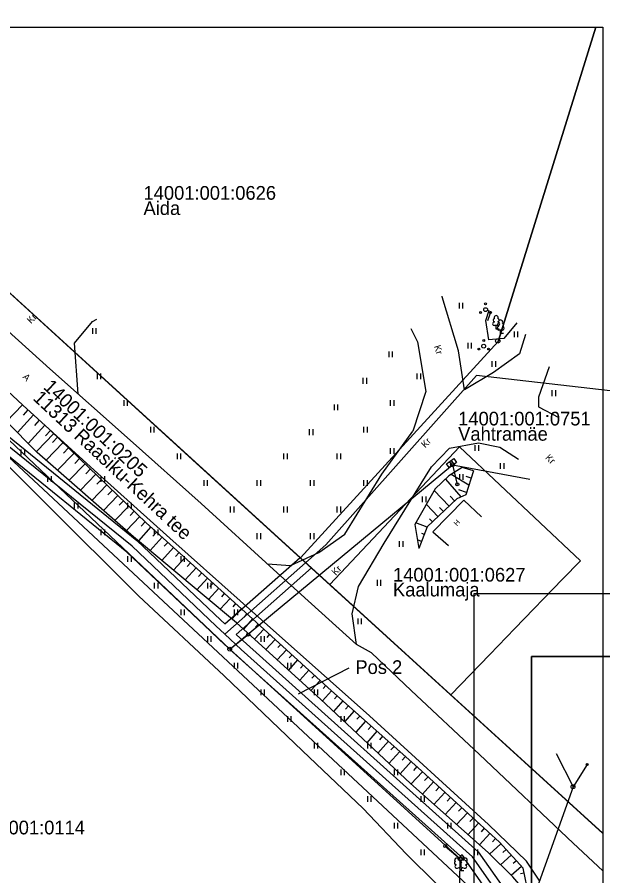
# Model space of a CAD drawing. Extents: x 567864 to 568657, y 6579839 to 6580994.
# Drawn here: x 568307.8 to 568384.7, y 6580491.9 to 6580604.7 of the extents above; entities that cross this region are included whole.
import ezdxf

# ---------------------------------------------------------------- set-up
doc = ezdxf.new("R2010")
doc.units = 0
for name, color, linetype in [('ELRAJATISMP', 7, 'Continuous'), ('HALJASTUS', 7, 'Continuous'), ('HOONE', 7, 'Continuous'), ('KASUTUSALA', 7, 'Continuous'), ('MPKAABEL', 7, 'Continuous'), ('MPOHULIIN', 7, 'Continuous'), ('PIIR', 7, 'Continuous'), ('PIIRIMLEITUD', 7, 'Continuous'), ('POST', 7, 'Continuous'), ('PR_SIDE', 7, 'Continuous'), ('PUU', 7, 'Continuous'), ('RELJEEF', 7, 'Continuous'), ('TEE', 7, 'Continuous'), ('VORMISTUS_2', 7, 'Continuous'), ('VORMISTUS_3', 7, 'Continuous')]:
    doc.layers.add(name, color=color, linetype=linetype)

msp = doc.modelspace()

# ---------------------------------------------------------------- linework, layer by layer
at = {"layer": 'ELRAJATISMP'}
for p, q in [((568364.53, 6580546.27), (568364.87, 6580545.78)), ((568364.75, 6580546.42), (568365.09, 6580545.94))]:
    msp.add_line(p, q, dxfattribs=at)
msp.add_lwpolyline([(568364.15, 6580546), (568365.13, 6580546.69), (568365.47, 6580546.2), (568364.49, 6580545.51)], close=True, dxfattribs=at)
at = {"layer": 'HALJASTUS'}
for p, q in [((568365.81, 6580567.15), (568365.81, 6580566.39)), ((568366.27, 6580567.15), (568366.27, 6580566.39)), ((568317.67, 6580563.82), (568317.67, 6580563.06)), ((568318.13, 6580563.82), (568318.13, 6580563.06)), ((568373.04, 6580563.4), (568373.04, 6580562.64)), ((568373.49, 6580563.4), (568373.49, 6580562.64)), ((568366.94, 6580561.91), (568366.94, 6580561.15)), ((568367.39, 6580561.91), (568367.39, 6580561.15)), ((568356.58, 6580560.76), (568356.58, 6580560)), ((568357.03, 6580560.76), (568357.03, 6580560)), ((568370.13, 6580559.5), (568370.13, 6580558.74)), ((568370.59, 6580559.5), (568370.59, 6580558.74)), ((568318.27, 6580557.88), (568318.27, 6580557.12)), ((568318.73, 6580557.88), (568318.73, 6580557.12)), ((568360.27, 6580557.88), (568360.27, 6580557.12)), ((568360.73, 6580557.88), (568360.73, 6580557.12)), ((568353.19, 6580557.28), (568353.19, 6580556.52)), ((568353.64, 6580557.28), (568353.64, 6580556.52)), ((568378, 6580555.66), (568378, 6580554.9)), ((568378.45, 6580555.66), (568378.45, 6580554.9)), ((568321.77, 6580554.38), (568321.77, 6580553.62)), ((568322.23, 6580554.38), (568322.23, 6580553.62)), ((568356.77, 6580554.38), (568356.77, 6580553.62)), ((568357.23, 6580554.38), (568357.23, 6580553.62)), ((568349.4, 6580553.81), (568349.4, 6580553.05)), ((568349.86, 6580553.81), (568349.86, 6580553.05)), ((568325.27, 6580550.88), (568325.27, 6580550.12)), ((568325.73, 6580550.88), (568325.73, 6580550.12)), ((568353.27, 6580550.88), (568353.27, 6580550.12)), ((568353.73, 6580550.88), (568353.73, 6580550.12)), ((568346.13, 6580550.54), (568346.13, 6580549.78)), ((568346.59, 6580550.54), (568346.59, 6580549.78)), ((568367.89, 6580548.45), (568367.89, 6580547.69)), ((568368.34, 6580548.45), (568368.34, 6580547.69)), ((568308.27, 6580547.88), (568308.27, 6580547.12)), ((568308.73, 6580547.88), (568308.73, 6580547.12)), ((568328.77, 6580547.38), (568328.77, 6580546.62)), ((568329.23, 6580547.38), (568329.23, 6580546.62)), ((568342.77, 6580547.38), (568342.77, 6580546.62)), ((568343.23, 6580547.38), (568343.23, 6580546.62)), ((568349.77, 6580547.38), (568349.77, 6580546.62)), ((568350.23, 6580547.38), (568350.23, 6580546.62)), ((568356.77, 6580548.07), (568356.77, 6580547.31)), ((568357.23, 6580548.07), (568357.23, 6580547.31)), ((568371.22, 6580546.1), (568371.22, 6580545.34)), ((568371.68, 6580546.1), (568371.68, 6580545.34)), ((568311.77, 6580544.38), (568311.77, 6580543.62)), ((568312.23, 6580544.38), (568312.23, 6580543.62)), ((568318.77, 6580544.38), (568318.77, 6580543.62)), ((568319.23, 6580544.38), (568319.23, 6580543.62)), ((568365.86, 6580544.65), (568365.86, 6580543.89)), ((568366.31, 6580544.65), (568366.31, 6580543.89)), ((568332.27, 6580543.88), (568332.27, 6580543.12)), ((568332.73, 6580543.88), (568332.73, 6580543.12)), ((568339.27, 6580543.88), (568339.27, 6580543.12)), ((568339.73, 6580543.88), (568339.73, 6580543.12)), ((568346.27, 6580543.88), (568346.27, 6580543.12)), ((568346.73, 6580543.88), (568346.73, 6580543.12)), ((568353.27, 6580543.88), (568353.27, 6580543.12)), ((568353.73, 6580543.88), (568353.73, 6580543.12)), ((568360.98, 6580541.72), (568360.98, 6580540.96)), ((568361.43, 6580541.72), (568361.43, 6580540.96)), ((568315.27, 6580540.88), (568315.27, 6580540.12)), ((568315.73, 6580540.88), (568315.73, 6580540.12)), ((568322.27, 6580540.88), (568322.27, 6580540.12)), ((568322.73, 6580540.88), (568322.73, 6580540.12)), ((568335.77, 6580540.38), (568335.77, 6580539.62)), ((568336.23, 6580540.38), (568336.23, 6580539.62)), ((568342.77, 6580540.38), (568342.77, 6580539.62)), ((568343.23, 6580540.38), (568343.23, 6580539.62)), ((568349.77, 6580540.38), (568349.77, 6580539.62)), ((568350.23, 6580540.38), (568350.23, 6580539.62)), ((568318.77, 6580537.38), (568318.77, 6580536.62)), ((568319.23, 6580537.38), (568319.23, 6580536.62)), ((568325.77, 6580537.38), (568325.77, 6580536.62)), ((568326.23, 6580537.38), (568326.23, 6580536.62)), ((568339.27, 6580536.88), (568339.27, 6580536.12)), ((568339.73, 6580536.88), (568339.73, 6580536.12)), ((568346.27, 6580536.88), (568346.27, 6580536.12)), ((568346.73, 6580536.88), (568346.73, 6580536.12)), ((568357.96, 6580535.87), (568357.96, 6580535.11)), ((568358.41, 6580535.87), (568358.41, 6580535.11)), ((568322.27, 6580533.88), (568322.27, 6580533.12)), ((568322.73, 6580533.88), (568322.73, 6580533.12)), ((568329.27, 6580533.88), (568329.27, 6580533.12)), ((568329.73, 6580533.88), (568329.73, 6580533.12)), ((568355.04, 6580530.76), (568355.04, 6580529.99)), ((568355.49, 6580530.76), (568355.49, 6580529.99)), ((568325.77, 6580530.38), (568325.77, 6580529.62)), ((568326.23, 6580530.38), (568326.23, 6580529.62)), ((568332.77, 6580530.38), (568332.77, 6580529.62)), ((568333.23, 6580530.38), (568333.23, 6580529.62)), ((568329.27, 6580526.88), (568329.27, 6580526.12)), ((568329.73, 6580526.88), (568329.73, 6580526.12)), ((568336.27, 6580526.88), (568336.27, 6580526.12)), ((568336.73, 6580526.88), (568336.73, 6580526.12)), ((568352.52, 6580525.69), (568352.52, 6580524.93)), ((568352.97, 6580525.69), (568352.97, 6580524.93)), ((568332.77, 6580523.38), (568332.77, 6580522.62)), ((568333.23, 6580523.38), (568333.23, 6580522.62)), ((568339.77, 6580523.38), (568339.77, 6580522.62)), ((568340.23, 6580523.38), (568340.23, 6580522.62)), ((568336.27, 6580519.88), (568336.27, 6580519.12)), ((568336.73, 6580519.88), (568336.73, 6580519.12)), ((568343.27, 6580519.88), (568343.27, 6580519.12)), ((568343.73, 6580519.88), (568343.73, 6580519.12)), ((568339.77, 6580516.38), (568339.77, 6580515.62)), ((568340.23, 6580516.38), (568340.23, 6580515.62)), ((568346.77, 6580516.38), (568346.77, 6580515.62)), ((568347.23, 6580516.38), (568347.23, 6580515.62)), ((568343.27, 6580512.88), (568343.27, 6580512.12)), ((568343.73, 6580512.88), (568343.73, 6580512.12)), ((568350.27, 6580512.88), (568350.27, 6580512.12)), ((568350.73, 6580512.88), (568350.73, 6580512.12)), ((568346.77, 6580509.38), (568346.77, 6580508.62)), ((568347.23, 6580509.38), (568347.23, 6580508.62)), ((568353.77, 6580509.38), (568353.77, 6580508.62)), ((568354.23, 6580509.38), (568354.23, 6580508.62)), ((568350.27, 6580505.88), (568350.27, 6580505.12)), ((568350.73, 6580505.88), (568350.73, 6580505.12)), ((568357.27, 6580505.88), (568357.27, 6580505.12)), ((568357.73, 6580505.88), (568357.73, 6580505.12)), ((568353.77, 6580502.38), (568353.77, 6580501.62)), ((568354.23, 6580502.38), (568354.23, 6580501.62)), ((568360.77, 6580502.38), (568360.77, 6580501.62)), ((568361.23, 6580502.38), (568361.23, 6580501.62)), ((568357.27, 6580498.88), (568357.27, 6580498.12)), ((568357.73, 6580498.88), (568357.73, 6580498.12)), ((568364.27, 6580498.88), (568364.27, 6580498.12)), ((568364.73, 6580498.88), (568364.73, 6580498.12)), ((568360.77, 6580495.38), (568360.77, 6580494.62)), ((568361.23, 6580495.38), (568361.23, 6580494.62)), ((568367.77, 6580495.38), (568367.77, 6580494.62)), ((568368.23, 6580495.38), (568368.23, 6580494.62))]:
    msp.add_line(p, q, dxfattribs=at)
for points in [[(568373.39, 6580564.53), (568371.7, 6580562.45), (568369.73, 6580562.3), (568369.32, 6580564.83), (568369.76, 6580566.16)], [(568369.59, 6580564.81), (568370.01, 6580566.05)]]:
    msp.add_lwpolyline(points, dxfattribs=at)
at = {"layer": 'HOONE'}
msp.add_lwpolyline([(568368.77, 6580539.04), (568366.43, 6580541.23), (568362.38, 6580537.07), (568364.42, 6580535.26)], dxfattribs=at)
at = {"layer": 'KASUTUSALA'}
msp.add_lwpolyline([(568371.56, 6580487.01), (568366.82, 6580493.74), (568336.54, 6580520.89), (568334.37, 6580522.89), (568333.16, 6580524.02), (568322.19, 6580534.42), (568305.67, 6580547.79), (568289.57, 6580562.8), (568275.19, 6580576.52), (568283.17, 6580571.11), (568291.95, 6580563.33), (568305.08, 6580550.84), (568323.51, 6580535.93), (568334.54, 6580525.48), (568335.07, 6580524.98), (568344.93, 6580533.71), (568344.98, 6580533.67), (568346.42, 6580532.36), (568336.55, 6580523.61), (568337.05, 6580523.13), (568337.88, 6580522.37), (568368.32, 6580495.08), (568373.24, 6580488.09)], dxfattribs=at)
at = {"layer": 'MPKAABEL'}
msp.add_lwpolyline([(568290.51, 6580580.15), (568289.47, 6580579.17), (568285.16, 6580574.37), (568283.84, 6580573.07), (568282.41, 6580571.53), (568281.92, 6580570.15), (568282.67, 6580568.89), (568289.46, 6580562.85), (568299.87, 6580552.42), (568311.62, 6580540.71), (568323.73, 6580528.68), (568334.96, 6580518.16), (568345.24, 6580508.32), (568353.21, 6580500.74), (568358.87, 6580494.79), (568362.88, 6580490.81), (568367.26, 6580487.78), (568369.74, 6580485.8), (568369.72, 6580484.3), (568368.69, 6580483.14), (568367.08, 6580481.93), (568366.32, 6580481.93), (568366.01, 6580481.86)], dxfattribs=at)
at = {"layer": 'MPOHULIIN'}
for points in [[(568335.69, 6580521.66), (568305, 6580550.67), (568273.62, 6580580.19), (568260.93, 6580591.97)], [(568365.79, 6580481.37), (568365.95, 6580494.12), (568335.69, 6580521.66), (568364.95, 6580545.89), (568375.08, 6580544.01)], [(568378.55, 6580507.96), (568380.77, 6580503.61), (568373.44, 6580483.03)]]:
    msp.add_lwpolyline(points, dxfattribs=at)
at = {"layer": 'PIIR'}
for points in [[(568268.46, 6580603.35), (568287.11, 6580586.34), (568330.81, 6580546.53), (568384.68, 6580497.48)], [(568383.76, 6580603.35), (568370.95, 6580562.05), (568344.98, 6580533.67), (568287.11, 6580586.34), (568302.89, 6580603.35)], [(568384.68, 6580497.49), (568364.73, 6580515.67), (568369.83, 6580520.95), (568373.15, 6580524.39), (568379.4, 6580530.86), (568381.74, 6580533.28), (568365.86, 6580548.23), (568348.84, 6580530.15), (568344.98, 6580533.67), (568370.95, 6580562.05), (568383.76, 6580603.35)], [(568384.68, 6580474.14), (568373.5, 6580484.56), (568289.57, 6580562.8), (568260.93, 6580590.14)], [(568260.93, 6580487.5), (568289.57, 6580562.8), (568373.5, 6580484.56), (568310.3, 6580445.85)]]:
    msp.add_lwpolyline(points, dxfattribs=at)
msp.add_lwpolyline([(568348.84, 6580530.15), (568365.86, 6580548.23), (568381.74, 6580533.28), (568379.4, 6580530.86), (568373.15, 6580524.39), (568369.83, 6580520.95), (568364.73, 6580515.67)], close=True, dxfattribs=at)
at = {"layer": 'PIIRIMLEITUD'}
msp.add_circle((568370.88, 6580562.14), 0.285, dxfattribs=at)
at = {"layer": 'POST'}
for p, q in [((568366.22, 6580494.65), (568365.99, 6580494.47)), ((568366.3, 6580494.07), (568365.99, 6580494.47)), ((568366.53, 6580494.25), (568366.22, 6580494.65)), ((568366.53, 6580494.25), (568366.3, 6580494.07))]:
    msp.add_line(p, q, dxfattribs=at)
for points in [[(568364.95, 6580545.89), (568365.58, 6580543.31)], [(568335.69, 6580521.66), (568338.13, 6580523.59)], [(568382.63, 6580506.54), (568380.77, 6580503.61)], [(568363.99, 6580495.82), (568365.95, 6580494.12)]]:
    msp.add_lwpolyline(points, dxfattribs=at)
for centre, radius in [((568364.95, 6580545.89), 0.25), ((568365.58, 6580543.31), 0.2), ((568338.13, 6580523.59), 0.2), ((568335.69, 6580521.66), 0.25), ((568382.63, 6580506.54), 0.125), ((568382.63, 6580506.54), 0.105), ((568382.63, 6580506.54), 0.0851), ((568382.63, 6580506.54), 0.0651), ((568382.63, 6580506.54), 0.0451), ((568382.63, 6580506.54), 0.0251), ((568382.63, 6580506.54), 0.00511), ((568380.77, 6580503.61), 0.25), ((568363.99, 6580495.82), 0.2), ((568365.95, 6580494.12), 0.25)]:
    msp.add_circle(centre, radius, dxfattribs=at)
at = {"layer": 'PR_SIDE'}
for points in [[(568372.77, 6580480.66), (568372.77, 6580480.66), (568372.77, 6580480.66), (568373.4, 6580481.36), (568374.25, 6580482.51), (568374.05, 6580484.04), (568373.82, 6580485.15), (568372.4, 6580487.55), (568367.57, 6580494.41), (568337.21, 6580521.63), (568335.06, 6580523.62), (568333.85, 6580524.75), (568322.86, 6580535.18), (568304.42, 6580550.09), (568291.27, 6580562.6), (568282.56, 6580570.32), (568277.09, 6580574.03), (568269.58, 6580580.5), (568245.73, 6580603.12), (568233.69, 6580614.91)], [(568401.09, 6580556.96), (568388.3, 6580555.28), (568368.11, 6580557.62), (568348.32, 6580535.38), (568335.06, 6580523.62)]]:
    msp.add_lwpolyline(points, dxfattribs=at)
at = {"layer": 'PUU'}
for p, q in [((568370.92, 6580564.15), (568370.44, 6580564.15)), ((568370.68, 6580563.67), (568370.68, 6580564.15)), ((568371.06, 6580563.67), (568370.68, 6580563.67)), ((568371.5, 6580563.57), (568371.02, 6580563.57)), ((568371.26, 6580563.1), (568371.26, 6580563.57)), ((568371.64, 6580563.1), (568371.26, 6580563.1)), ((568365.6, 6580492.91), (568366.04, 6580493.09)), ((568366.04, 6580492.58), (568365.86, 6580493.02)), ((568366.04, 6580493.09), (568366.48, 6580492.91)), ((568366.04, 6580492.58), (568366.22, 6580493.02)), ((568366.42, 6580492.58), (568366.04, 6580492.58))]:
    msp.add_line(p, q, dxfattribs=at)
msp.add_lwpolyline([(568366.04, 6580493.58), (568366.02, 6580493.51), (568366.02, 6580493.49), (568366.03, 6580493.46), (568366.05, 6580493.42), (568366.06, 6580493.4), (568366.04, 6580493.37), (568366.02, 6580493.32), (568366.01, 6580493.29), (568366.02, 6580493.28), (568366.03, 6580493.25), (568366.06, 6580493.19), (568366.07, 6580493.17), (568366.06, 6580493.15), (568366.05, 6580493.11), (568366.04, 6580493.09)], dxfattribs=at)
for centre, radius in [((568369.29, 6580566.25), 0.25), ((568369.29, 6580567), 0.125), ((568368.64, 6580565.87), 0.125), ((568369.94, 6580565.87), 0.125), ((568369.04, 6580562.2), 0.125), ((568368.39, 6580561.08), 0.125), ((568369.04, 6580561.45), 0.25), ((568369.69, 6580561.08), 0.125)]:
    msp.add_circle(centre, radius, dxfattribs=at)
for centre, radius, start, end in [((568370.68, 6580565.19), 0.277, 332.5799, 207.4201), ((568370.44, 6580564.39), 0.238, 90.0016, 269.3953), ((568370.51, 6580564.85), 0.233, 109.0217, 253.1415), ((568371.09, 6580564.27), 0.233, 109.0217, 253.1415), ((568370.85, 6580564.85), 0.233, 286.8508, 70.9859), ((568370.91, 6580564.39), 0.238, 270.6047, 89.9984), ((568371.26, 6580564.62), 0.277, 332.5799, 207.4201), ((568371.43, 6580564.27), 0.233, 286.8508, 70.9859), ((568371.03, 6580563.81), 0.238, 90.0016, 269.3953), ((568371.5, 6580563.81), 0.238, 270.6047, 89.9984), ((568365.41, 6580493.58), 0.224, 111.4304, 274.4987), ((568365.48, 6580493.99), 0.256, 111.5027, 232.5173), ((568365.51, 6580493.14), 0.237, 111.5014, 291.5004), ((568365.48, 6580493.99), 0.256, 350.4856, 111.5002), ((568365.82, 6580493.74), 0.224, 308.5041, 111.5725), ((568366.04, 6580493.34), 0.237, 66.7655, 111.5015), ((568366.28, 6580493.74), 0.225, 67.7016, 230.5126), ((568366.62, 6580493.98), 0.256, 67.6168, 188.6314), ((568366.57, 6580493.13), 0.237, 247.6166, 67.6155), ((568366.69, 6580493.57), 0.224, 264.6183, 67.6866), ((568366.62, 6580493.98), 0.256, 306.5997, 67.6143)]:
    msp.add_arc(centre, radius, start, end, dxfattribs=at)
at = {"layer": 'RELJEEF'}
for p, q in [((568308.46, 6580553.77), (568306.39, 6580551.54)), ((568309.2, 6580553.09), (568308.58, 6580552.41)), ((568309.94, 6580552.42), (568307.83, 6580550.1)), ((568311.42, 6580551.07), (568309.24, 6580548.68)), ((568310.68, 6580551.75), (568310.04, 6580551.04)), ((568312.59, 6580549.98), (568310.36, 6580547.66)), ((568312.16, 6580550.4), (568311.49, 6580549.67)), ((568313.81, 6580548.8), (568311.58, 6580546.49)), ((568313.09, 6580549.5), (568312.41, 6580548.79)), ((568315.25, 6580547.41), (568313.08, 6580545.17)), ((568314.53, 6580548.11), (568313.87, 6580547.42)), ((568315.97, 6580546.72), (568315.33, 6580546.05)), ((568316.69, 6580546.02), (568314.59, 6580543.85)), ((568317.41, 6580545.33), (568316.79, 6580544.69)), ((568367.71, 6580545.09), (568367.71, 6580545.09)), ((568318.13, 6580544.63), (568316.09, 6580542.53)), ((568318.84, 6580543.94), (568318.25, 6580543.32)), ((568366.07, 6580541.65), (568364.05, 6580544.01)), ((568367.09, 6580543.19), (568364.78, 6580544.6)), ((568367.4, 6580544.14), (568366.74, 6580544.36)), ((568319.56, 6580543.24), (568317.6, 6580541.21)), ((568321, 6580541.85), (568319.1, 6580539.89)), ((568320.28, 6580542.55), (568319.7, 6580541.95)), ((568364.51, 6580540.43), (568362.56, 6580542.49)), ((568365.24, 6580541.11), (568364.64, 6580541.75)), ((568366.78, 6580542.24), (568365.76, 6580542.58)), ((568321.72, 6580541.16), (568321.16, 6580540.58)), ((568363.06, 6580539.05), (568361.53, 6580540.67)), ((568322.44, 6580540.46), (568320.61, 6580538.57)), ((568323.16, 6580539.77), (568322.62, 6580539.21)), ((568363.78, 6580539.74), (568363.26, 6580540.29)), ((568323.88, 6580539.07), (568322.12, 6580537.25)), ((568324.6, 6580538.38), (568324.08, 6580537.84)), ((568362.33, 6580538.37), (568361.93, 6580538.79)), ((568325.34, 6580537.71), (568323.7, 6580535.89)), ((568361.62, 6580537.67), (568360.15, 6580538.24)), ((568326.82, 6580536.36), (568325.23, 6580534.61)), ((568326.08, 6580537.03), (568325.59, 6580536.5)), ((568361.26, 6580536.74), (568360.93, 6580536.86)), ((568328.31, 6580535.02), (568326.77, 6580533.32)), ((568327.56, 6580535.69), (568327.09, 6580535.18)), ((568360.89, 6580535.81), (568360.35, 6580536.02)), ((568329.05, 6580534.35), (568328.59, 6580533.85)), ((568329.79, 6580533.68), (568328.3, 6580532.04)), ((568330.53, 6580533.01), (568330.09, 6580532.53)), ((568331.27, 6580532.34), (568329.84, 6580530.76)), ((568332.02, 6580531.67), (568331.59, 6580531.2)), ((568332.76, 6580531), (568331.38, 6580529.47)), ((568334.24, 6580529.66), (568332.91, 6580528.19)), ((568333.5, 6580530.33), (568333.09, 6580529.88)), ((568335.73, 6580528.32), (568334.45, 6580526.91)), ((568334.98, 6580528.99), (568334.59, 6580528.56)), ((568336.47, 6580527.65), (568336.09, 6580527.23)), ((568337.21, 6580526.98), (568335.98, 6580525.62)), ((568337.95, 6580526.31), (568337.59, 6580525.91)), ((568338.69, 6580525.63), (568337.48, 6580524.31)), ((568339.43, 6580524.96), (568339.07, 6580524.56)), ((568340.17, 6580524.29), (568338.96, 6580522.96)), ((568341.65, 6580522.94), (568340.44, 6580521.62)), ((568340.91, 6580523.62), (568340.55, 6580523.22)), ((568343.13, 6580521.6), (568341.92, 6580520.27)), ((568342.39, 6580522.27), (568342.03, 6580521.87)), ((568344.61, 6580520.25), (568343.4, 6580518.93)), ((568343.87, 6580520.92), (568343.51, 6580520.53)), ((568345.35, 6580519.58), (568344.99, 6580519.18)), ((568346.09, 6580518.9), (568344.88, 6580517.58)), ((568346.83, 6580518.23), (568346.47, 6580517.84)), ((568347.57, 6580517.56), (568346.36, 6580516.24)), ((568348.31, 6580516.89), (568347.95, 6580516.49)), ((568349.05, 6580516.21), (568347.86, 6580514.87)), ((568350.54, 6580514.88), (568349.31, 6580513.5)), ((568349.79, 6580515.55), (568349.43, 6580515.14)), ((568352.04, 6580513.56), (568350.77, 6580512.13)), ((568351.29, 6580514.22), (568350.91, 6580513.8)), ((568352.78, 6580512.89), (568352.4, 6580512.46)), ((568353.53, 6580512.23), (568352.23, 6580510.76)), ((568354.28, 6580511.56), (568353.88, 6580511.12)), ((568355.03, 6580510.9), (568353.69, 6580509.39)), ((568355.77, 6580510.23), (568355.37, 6580509.78)), ((568356.52, 6580509.57), (568355.14, 6580508.02)), ((568358.02, 6580508.24), (568356.6, 6580506.65)), ((568357.27, 6580508.91), (568356.85, 6580508.43)), ((568359.51, 6580506.91), (568358.06, 6580505.28)), ((568358.76, 6580507.58), (568358.33, 6580507.09)), ((568360.26, 6580506.25), (568359.82, 6580505.75)), ((568361, 6580505.58), (568359.49, 6580503.93)), ((568361.73, 6580504.9), (568361.29, 6580504.41)), ((568362.47, 6580504.23), (568360.99, 6580502.61)), ((568363.21, 6580503.55), (568362.77, 6580503.07)), ((568363.95, 6580502.87), (568362.49, 6580501.28)), ((568365.42, 6580501.52), (568363.98, 6580499.95)), ((568364.68, 6580502.2), (568364.25, 6580501.72)), ((568366.9, 6580500.17), (568365.48, 6580498.63)), ((568366.16, 6580500.85), (568365.73, 6580500.38)), ((568367.64, 6580499.5), (568367.21, 6580499.04)), ((568368.37, 6580498.82), (568366.98, 6580497.3)), ((568369.11, 6580498.15), (568368.69, 6580497.69)), ((568369.85, 6580497.47), (568368.47, 6580495.97)), ((568370.59, 6580496.8), (568370.18, 6580496.35)), ((568371.3, 6580496.1), (568369.82, 6580494.75)), ((568372.65, 6580494.63), (568371.25, 6580493.34)), ((568371.98, 6580495.37), (568371.55, 6580494.97)), ((568373.33, 6580493.89), (568372.92, 6580493.51)), ((568374, 6580493.15), (568372.67, 6580491.93)), ((568374.36, 6580492.25), (568373.86, 6580492.15))]:
    msp.add_line(p, q, dxfattribs=at)
for points in [[(568310.42, 6580547.5), (568302.1, 6580555.85), (568296.22, 6580561.96), (568282.93, 6580574.8), (568274.07, 6580582.75), (568263.63, 6580594.9)], [(568374.98, 6580489.31), (568374.23, 6580492.9), (568371.11, 6580496.32), (568360.39, 6580506.13), (568349.04, 6580516.21), (568337.24, 6580526.96), (568324.74, 6580538.25), (568312.16, 6580550.4)], [(568374.98, 6580489.31), (568372.85, 6580491.76), (568369.62, 6580494.95), (568359.41, 6580504.01), (568347.61, 6580515.1), (568336.57, 6580525.13), (568323.07, 6580536.41), (568310.42, 6580547.5)], [(568367.71, 6580545.09), (568366.22, 6580545.52), (568364.48, 6580544.41), (568362.69, 6580542.72), (568360.02, 6580538.02), (568360.54, 6580534.9)], [(568367.71, 6580545.09), (568366.68, 6580541.94), (568365.53, 6580541.39), (568361.64, 6580537.72), (568360.54, 6580534.9)]]:
    msp.add_lwpolyline(points, dxfattribs=at)
at = {"layer": 'TEE'}
for points in [[(568384.68, 6580492.57), (568380.78, 6580496.19), (568368.5, 6580507.85), (568359.52, 6580516.22), (568354.33, 6580521.19), (568352.36, 6580522.29), (568341.44, 6580532.14), (568331.96, 6580540.8), (568322.6, 6580549.12), (568312.08, 6580558.49), (568303.36, 6580566.33), (568291.02, 6580577.44), (568278.67, 6580588.56), (568266.39, 6580600.24), (568263.55, 6580603.35)], [(568376.41, 6580491.21), (568374.68, 6580493.82), (568369.68, 6580498.66), (568354.03, 6580512.91), (568337.06, 6580528.03), (568327.84, 6580536.25), (568318.37, 6580544.73), (568308.51, 6580553.72), (568297.84, 6580563.66), (568283.77, 6580576.45), (568275.34, 6580584.27), (568263.63, 6580594.9), (568260.93, 6580597.38)], [(568374.53, 6580562.97), (568373.75, 6580560.46), (568370.31, 6580557.99), (568366.51, 6580555.71), (568365.72, 6580560.82), (568363.61, 6580567.91), (568363.58, 6580568.03)], [(568315.78, 6580555.19), (568315.29, 6580561.86), (568317.66, 6580564.71), (568318.26, 6580565)], [(568359.47, 6580563.77), (568360.33, 6580562.03), (568361.44, 6580555.48), (568359.73, 6580550.3)], [(568377.63, 6580558.73), (568376.25, 6580554.77), (568376.25, 6580553.49), (568378.89, 6580552.1)], [(568340.65, 6580532.86), (568343.69, 6580532.66), (568347.39, 6580534.34), (568350.8, 6580536.78), (568355.66, 6580544.63), (568359.73, 6580550.3)], [(568352.36, 6580522.29), (568351.77, 6580526.29), (568352.59, 6580529.89), (568355.96, 6580535.58), (568362.17, 6580545.61), (568364.53, 6580548.06), (568368.36, 6580548.76), (568371.16, 6580548.18), (568373.62, 6580546.61)]]:
    msp.add_lwpolyline(points, dxfattribs=at)
at = {"layer": 'VORMISTUS_2'}
msp.add_line((568344.73, 6580515.81), (568351.39, 6580519.22), dxfattribs=at)
msp.add_lwpolyline([(568384.68, 6580445.85), (568260.93, 6580445.85), (568260.93, 6580603.35), (568384.68, 6580603.35)], close=True, dxfattribs=at)
at = {"layer": 'VORMISTUS_3'}
for points in [[(568367.8, 6580528.96), (568525.3, 6580528.96), (568525.3, 6580306.21), (568367.8, 6580306.21)], [(568375.3, 6580314.46), (568517.8, 6580314.46), (568517.8, 6580520.71), (568375.3, 6580520.71)], [(568375.3, 6580520.71), (568517.8, 6580520.71), (568517.8, 6580314.46), (568375.3, 6580314.46)]]:
    msp.add_lwpolyline(points, close=True, dxfattribs=at)

# ---------------------------------------------------------------- texts
at = {"layer": 'HOONE'}
msp.add_text('H', height=0.7, rotation=47.6705, dxfattribs=at).set_placement((568365.54, 6580537.78))
at = {"layer": 'PIIR'}
for s, p in [('14001:001:0626', (568324.37, 6580580.68)), ('Aida', (568324.37, 6580578.68)), ('14001:001:0751', (568365.69, 6580551.04)), ('Vahtramäe', (568365.69, 6580549.04)), ('14001:001:0627', (568357.13, 6580530.54)), ('Kaalumaja', (568357.13, 6580528.59)), ('14001:001:0114', (568299.28, 6580497.35))]:
    msp.add_text(s, height=1.8, dxfattribs=at).set_placement(p)
for s, p in [('14001:001:0205', (568311.11, 6580555.96)), ('11313 Raasiku-Kehra tee', (568309.74, 6580554.5))]:
    msp.add_text(s, height=1.8, rotation=316.9533, dxfattribs=at).set_placement(p)
at = {"layer": 'TEE'}
for s, rotation, p in [('Kr', 45.288, (568309.59, 6580564.34)), ('Kr', 287.7345, (568362.49, 6580561.43)), ('A', 315.2576, (568308.41, 6580557.33)), ('Kr', 45.288, (568361.37, 6580548.03)), ('Kr', 315.288, (568377.06, 6580546.73)), ('Kr', 45.288, (568349.61, 6580531.28))]:
    msp.add_text(s, height=0.9, rotation=rotation, dxfattribs=at).set_placement(p)
at = {"layer": 'VORMISTUS_2'}
msp.add_text('Pos 2', height=1.8, dxfattribs=at).set_placement((568352.19, 6580518.41))

doc.saveas('drawing.dxf')
